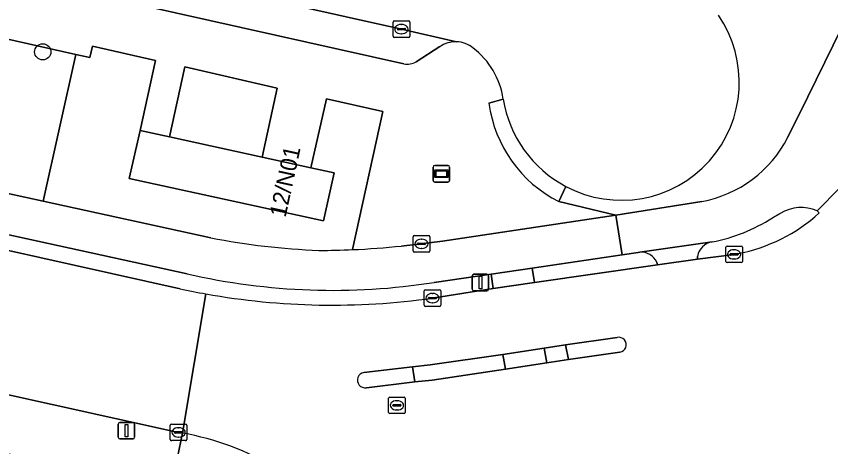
# Model space of a CAD drawing. Extents: x 162172 to 163187, y 382874 to 383685.
# Drawn here: x 163091.57 to 163140.66, y 383050.22 to 383076.16 of the extents above; entities that cross this region are included whole.
import ezdxf

# ---------------------------------------------------------------- set-up
doc = ezdxf.new("R2010")
doc.units = 0
for name, color, linetype in [('IMGEO_Boom', 7, 'Continuous'), ('IMGEO_Fietspad_gesloten', 7, 'Continuous'), ('IMGEO_Fietspad_open', 7, 'Continuous'), ('IMGEO_Groenvoorziening', 7, 'Continuous'), ('IMGEO_Kolk', 7, 'Continuous'), ('IMGEO_Lichtmast', 7, 'Continuous'), ('IMGEO_Pand', 7, 'Continuous'), ('IMGEO_Pand_nummerreeks', 7, 'Continuous'), ('IMGEO_Parkeervlak_open', 7, 'Continuous'), ('IMGEO_Reclamebord', 7, 'Continuous'), ('IMGEO_Rijbaan_lokaal_open', 7, 'Continuous'), ('IMGEO_Rioolput', 7, 'Continuous'), ('IMGEO_Verkeerseiland_open', 7, 'Continuous'), ('IMGEO_Voetpad_open', 7, 'Continuous')]:
    doc.layers.add(name, color=color, linetype=linetype)

msp = doc.modelspace()

# ---------------------------------------------------------------- linework, layer by layer
at = {"layer": 'IMGEO_Boom'}
msp.add_circle((163093.168, 383074.016), 0.489, dxfattribs=at)
at = {"layer": 'IMGEO_Fietspad_gesloten'}
for points in [[(163141.655, 383070.479), (163142.74, 383072.633), (163146.448, 383080.356), (163148.365, 383084.318), (163146.149, 383085.407), (163145.965, 383085.037), (163145.894, 383084.798), (163139.273, 383071.309), (163138.078, 383068.874)], [(163139.843, 383064.427), (163142.592, 383067.222)], [(163132.882, 383064.992), (163127.711, 383064.172), (163128.08, 383061.776), (163129.047, 383061.92), (163129.15, 383061.935), (163133.511, 383062.561)], [(163137.148, 383064.014), (163137.618, 383064.27)]]:
    msp.add_lwpolyline(points, dxfattribs=at)
for centre, radius, start, end in [((163131.517, 383072.237), 7.372, 280.6668, 332.861), ((163138.875, 383062.299), 2.338, 65.5429, 122.5295), ((163131.558, 383072.727), 10.352, 280.873, 302.681)]:
    msp.add_arc(centre, radius, start, end, dxfattribs=at)
at = {"layer": 'IMGEO_Fietspad_open'}
for points in [[(163103.293, 383062.808), (163093.192, 383065.008), (163090.977, 383065.49), (163082.089, 383067.416), (163081.762, 383067.487), (163081.303, 383067.542), (163068.825, 383068.129), (163068.711, 383065.723), (163080.79, 383065.134), (163081.09, 383065.184), (163101.866, 383060.645)], [(163116.758, 383060.123), (163120.185, 383060.622), (163122.671, 383060.982), (163128.08, 383061.776), (163127.711, 383064.172), (163117.252, 383062.615), (163114.786, 383062.314)], [(163133.511, 383062.561), (163129.15, 383061.935)], [(163130.176, 383061.332), (163130.212, 383061.172), (163132.626, 383061.518), (163132.623, 383061.691)]]:
    msp.add_lwpolyline(points, dxfattribs=at)
for centre, radius, start, end in [((163111.44, 383104.583), 42.562, 258.9647, 267.8134), ((163133.678, 383061.503), 1.072, 98.957, 169.8698), ((163109.817, 383108.459), 46.407, 269.9992, 272.4952), ((163109.816, 383109.488), 47.435, 272.4416, 276.014), ((163129.244, 383060.921), 1.019, 23.8194, 95.2934), ((163110.657, 383098.743), 39.099, 257.0073, 278.9777)]:
    msp.add_arc(centre, radius, start, end, dxfattribs=at)
at = {"layer": 'IMGEO_Groenvoorziening'}
for points in [[(163083.826, 383075.447), (163082.948, 383071.199), (163082.089, 383067.416), (163090.977, 383065.49), (163093.192, 383065.008), (163095.164, 383073.865), (163084.973, 383076.149)], [(163111.837, 383062.096), (163113.664, 383070.428), (163110.26, 383071.188), (163109.324, 383067.025), (163110.721, 383066.718), (163110.085, 383063.826), (163098.375, 383066.376), (163099.033, 383069.286), (163099.956, 383073.497), (163096.159, 383074.363), (163096.009, 383073.676), (163095.164, 383073.865), (163093.192, 383065.008), (163103.293, 383062.808)]]:
    msp.add_lwpolyline(points, dxfattribs=at)
msp.add_lwpolyline([(163106.386, 383067.671), (163107.298, 383071.823), (163101.738, 383073.108), (163100.799, 383068.898)], close=True, dxfattribs=at)
for centre, radius, start, end in [((163111.44, 383104.583), 42.562, 258.9647, 267.8134), ((163109.817, 383108.459), 46.407, 269.9992, 272.4952)]:
    msp.add_arc(centre, radius, start, end, dxfattribs=at)
at = {"layer": 'IMGEO_Kolk'}
for p, q in [((163114.282, 383074.961), (163114.282, 383075.813)), ((163114.357, 383075.887), (163115.209, 383075.887)), ((163114.77, 383075.667), (163114.795, 383075.667)), ((163115.283, 383075.813), (163115.283, 383074.961)), ((163114.541, 383075.381), (163114.541, 383075.393)), ((163114.979, 383075.344), (163114.581, 383075.344)), ((163114.584, 383075.43), (163114.982, 383075.43)), ((163115.025, 383075.393), (163115.025, 383075.381)), ((163115.209, 383074.887), (163114.357, 383074.887)), ((163114.793, 383075.107), (163114.768, 383075.107)), ((163115.57, 383062.946), (163116.422, 383062.946)), ((163115.495, 383062.02), (163115.495, 383062.872)), ((163115.754, 383062.44), (163115.754, 383062.452)), ((163116.192, 383062.403), (163115.794, 383062.403)), ((163115.797, 383062.489), (163116.195, 383062.489)), ((163115.983, 383062.726), (163116.008, 383062.726)), ((163116.238, 383062.452), (163116.238, 383062.44)), ((163116.496, 383062.872), (163116.496, 383062.02)), ((163116.422, 383061.946), (163115.57, 383061.946)), ((163116.006, 383062.166), (163115.981, 383062.166)), ((163134.333, 383061.387), (163134.333, 383062.239)), ((163134.408, 383062.313), (163135.26, 383062.313)), ((163134.821, 383062.093), (163134.846, 383062.093)), ((163135.334, 383062.239), (163135.334, 383061.387)), ((163134.592, 383061.807), (163134.592, 383061.819)), ((163135.03, 383061.77), (163134.632, 383061.77)), ((163134.635, 383061.856), (163135.033, 383061.856)), ((163134.844, 383061.533), (163134.819, 383061.533)), ((163135.076, 383061.819), (163135.076, 383061.807)), ((163135.26, 383061.313), (163134.408, 383061.313)), ((163116.156, 383058.753), (163116.156, 383059.605)), ((163116.231, 383059.679), (163117.083, 383059.679)), ((163116.644, 383059.459), (163116.669, 383059.459)), ((163117.157, 383059.605), (163117.157, 383058.753)), ((163116.415, 383059.173), (163116.415, 383059.185)), ((163116.853, 383059.136), (163116.455, 383059.136)), ((163116.458, 383059.222), (163116.856, 383059.222)), ((163116.899, 383059.185), (163116.899, 383059.173)), ((163117.083, 383058.679), (163116.231, 383058.679)), ((163116.667, 383058.899), (163116.642, 383058.899)), ((163100.853, 383050.659), (163100.853, 383051.511)), ((163100.928, 383051.585), (163101.78, 383051.585)), ((163101.155, 383051.128), (163101.553, 383051.128)), ((163101.341, 383051.365), (163101.366, 383051.365)), ((163101.854, 383051.511), (163101.854, 383050.659)), ((163101.112, 383051.079), (163101.112, 383051.091)), ((163101.55, 383051.042), (163101.152, 383051.042)), ((163101.364, 383050.805), (163101.339, 383050.805)), ((163101.596, 383051.091), (163101.596, 383051.079)), ((163101.78, 383050.585), (163100.928, 383050.585))]:
    msp.add_line(p, q, dxfattribs=at)
for points in [[(163114.282, 383074.961), (163114.282, 383075.813)], [(163114.357, 383075.887), (163115.209, 383075.887)], [(163115.283, 383075.813), (163115.283, 383074.961)], [(163115.209, 383074.887), (163114.357, 383074.887)], [(163115.57, 383062.946), (163116.422, 383062.946)], [(163115.495, 383062.02), (163115.495, 383062.872)], [(163116.496, 383062.872), (163116.496, 383062.02)], [(163116.422, 383061.946), (163115.57, 383061.946)], [(163134.333, 383061.387), (163134.333, 383062.239)], [(163134.408, 383062.313), (163135.26, 383062.313)], [(163135.334, 383062.239), (163135.334, 383061.387)], [(163135.26, 383061.313), (163134.408, 383061.313)], [(163116.156, 383058.753), (163116.156, 383059.605)], [(163116.231, 383059.679), (163117.083, 383059.679)], [(163117.157, 383059.605), (163117.157, 383058.753)], [(163117.083, 383058.679), (163116.231, 383058.679)], [(163100.853, 383050.659), (163100.853, 383051.511)], [(163100.928, 383051.585), (163101.78, 383051.585)], [(163101.854, 383051.511), (163101.854, 383050.659)], [(163101.78, 383050.585), (163100.928, 383050.585)]]:
    msp.add_lwpolyline(points, dxfattribs=at)
for centre, radius, start, end in [((163114.359, 383075.811), 0.0765, 91.552, 178.448), ((163114.359, 383075.811), 0.0765, 91.552, 178.448), ((163115.207, 383075.811), 0.0765, 1.552, 88.448), ((163115.207, 383075.811), 0.0765, 1.552, 88.448), ((163114.581, 383075.39), 0.0403, 85.8775, 175.7526), ((163114.578, 383075.38), 0.0366, 178.938, 274.7102), ((163114.982, 383075.387), 0.043, 264.8664, 352.4533), ((163114.986, 383075.392), 0.0386, 1.7309, 96.639), ((163114.359, 383074.963), 0.0765, 181.552, 268.448), ((163114.359, 383074.963), 0.0765, 181.552, 268.448), ((163115.207, 383074.963), 0.0765, 271.552, 358.448), ((163115.207, 383074.963), 0.0765, 271.552, 358.448), ((163115.572, 383062.87), 0.0765, 91.552, 178.448), ((163115.572, 383062.87), 0.0765, 91.552, 178.448), ((163116.42, 383062.87), 0.0765, 1.552, 88.448), ((163116.42, 383062.87), 0.0765, 1.552, 88.448), ((163115.794, 383062.449), 0.0403, 85.8775, 175.7526), ((163115.791, 383062.439), 0.0366, 178.938, 274.7102), ((163116.195, 383062.446), 0.043, 264.8664, 352.4533), ((163116.199, 383062.451), 0.0386, 1.7309, 96.639), ((163115.572, 383062.022), 0.0765, 181.552, 268.448), ((163115.572, 383062.022), 0.0765, 181.552, 268.448), ((163116.42, 383062.022), 0.0765, 271.552, 358.448), ((163116.42, 383062.022), 0.0765, 271.552, 358.448), ((163134.41, 383062.237), 0.0765, 91.552, 178.448), ((163134.41, 383062.237), 0.0765, 91.552, 178.448), ((163135.258, 383062.237), 0.0765, 1.552, 88.448), ((163135.258, 383062.237), 0.0765, 1.552, 88.448), ((163134.632, 383061.816), 0.0403, 85.8775, 175.7526), ((163134.629, 383061.806), 0.0366, 178.938, 274.7102), ((163135.033, 383061.813), 0.043, 264.8664, 352.4533), ((163135.037, 383061.818), 0.0386, 1.7309, 96.639), ((163134.41, 383061.389), 0.0765, 181.552, 268.448), ((163134.41, 383061.389), 0.0765, 181.552, 268.448), ((163135.258, 383061.389), 0.0765, 271.552, 358.448), ((163135.258, 383061.389), 0.0765, 271.552, 358.448), ((163116.233, 383059.603), 0.0765, 91.552, 178.448), ((163116.233, 383059.603), 0.0765, 91.552, 178.448), ((163117.081, 383059.603), 0.0765, 1.552, 88.448), ((163117.081, 383059.603), 0.0765, 1.552, 88.448), ((163116.455, 383059.182), 0.0403, 85.8775, 175.7526), ((163116.452, 383059.172), 0.0366, 178.938, 274.7102), ((163116.856, 383059.179), 0.043, 264.8664, 352.4533), ((163116.86, 383059.184), 0.0386, 1.7309, 96.639), ((163116.233, 383058.755), 0.0765, 181.552, 268.448), ((163116.233, 383058.755), 0.0765, 181.552, 268.448), ((163117.081, 383058.755), 0.0765, 271.552, 358.448), ((163117.081, 383058.755), 0.0765, 271.552, 358.448), ((163100.93, 383051.509), 0.0765, 91.552, 178.448), ((163100.93, 383051.509), 0.0765, 91.552, 178.448), ((163101.152, 383051.088), 0.0403, 85.8775, 175.7526), ((163101.557, 383051.09), 0.0386, 1.7309, 96.639), ((163101.778, 383051.509), 0.0765, 1.552, 88.448), ((163101.778, 383051.509), 0.0765, 1.552, 88.448), ((163100.93, 383050.661), 0.0765, 181.552, 268.448), ((163100.93, 383050.661), 0.0765, 181.552, 268.448), ((163101.149, 383051.078), 0.0366, 178.938, 274.7102), ((163101.553, 383051.085), 0.043, 264.8664, 352.4533), ((163101.778, 383050.661), 0.0765, 271.552, 358.448), ((163101.778, 383050.661), 0.0765, 271.552, 358.448)]:
    msp.add_arc(centre, radius, start, end, dxfattribs=at)
for centre, major_axis, ratio, start_param, end_param in [((163114.769, 383075.387), (-0.387, 0.002), 0.722429, 4.712389, 7.853982), ((163114.794, 383075.387), (-0.39, 0.002), 0.717154, 1.570796, 4.712389), ((163115.982, 383062.446), (-0.387, 0.002), 0.722429, 4.712389, 7.853982), ((163116.007, 383062.446), (-0.39, 0.002), 0.717154, 1.570796, 4.712389), ((163134.82, 383061.813), (-0.387, 0.002), 0.722429, 4.712389, 7.853982), ((163134.845, 383061.813), (-0.39, 0.002), 0.717154, 1.570796, 4.712389), ((163116.643, 383059.179), (-0.387, 0.002), 0.722429, 4.712389, 7.853982), ((163116.668, 383059.179), (-0.39, 0.002), 0.717154, 1.570796, 4.712389), ((163101.34, 383051.085), (-0.387, 0.002), 0.722429, 4.712389, 7.853982), ((163101.365, 383051.085), (-0.39, 0.002), 0.717154, 1.570796, 4.712389)]:
    msp.add_ellipse(centre, major_axis=major_axis, ratio=ratio, start_param=start_param, end_param=end_param, dxfattribs=at)
at = {"layer": 'IMGEO_Lichtmast'}
for p, q in [((163119.051, 383059.713), (163119.051, 383060.513)), ((163119.051, 383060.513), (163119.051, 383059.713)), ((163119.151, 383060.613), (163119.941, 383060.613)), ((163119.941, 383060.613), (163119.151, 383060.613)), ((163120.041, 383060.513), (163120.041, 383059.713)), ((163120.041, 383059.713), (163120.041, 383060.513)), ((163119.941, 383059.613), (163119.151, 383059.613)), ((163119.151, 383059.613), (163119.941, 383059.613)), ((163097.817, 383051.686), (163098.607, 383051.686)), ((163098.607, 383051.686), (163097.817, 383051.686)), ((163097.717, 383050.786), (163097.717, 383051.586)), ((163097.717, 383051.586), (163097.717, 383050.786)), ((163098.707, 383051.586), (163098.707, 383050.786)), ((163098.707, 383050.786), (163098.707, 383051.586)), ((163098.607, 383050.686), (163097.817, 383050.686)), ((163097.817, 383050.686), (163098.607, 383050.686))]:
    msp.add_line(p, q, dxfattribs=at)
for points in [[(163119.471, 383060.488), (163119.621, 383060.488), (163119.621, 383059.738), (163119.471, 383059.738), (163119.471, 383060.488)], [(163098.137, 383051.561), (163098.287, 383051.561), (163098.287, 383050.811), (163098.137, 383050.811), (163098.137, 383051.561)]]:
    msp.add_lwpolyline(points, dxfattribs=at)
for centre, start, end in [((163119.151, 383060.513), 90, 180), ((163119.151, 383060.513), 90, 180), ((163119.941, 383060.513), 0, 90), ((163119.941, 383060.513), 360, 90), ((163119.151, 383059.713), 180, 270), ((163119.151, 383059.713), 180, 270), ((163119.941, 383059.713), 270, 0), ((163119.941, 383059.713), 270, 0), ((163097.817, 383051.586), 90, 180), ((163097.817, 383051.586), 90, 180), ((163098.607, 383051.586), 0, 90), ((163098.607, 383051.586), 360, 90), ((163097.817, 383050.786), 180, 270), ((163097.817, 383050.786), 180, 270), ((163098.607, 383050.786), 270, 0), ((163098.607, 383050.786), 270, 0)]:
    msp.add_arc(centre, 0.1, start, end, dxfattribs=at)
at = {"layer": 'IMGEO_Pand'}
msp.add_lwpolyline([(163106.386, 383067.671), (163100.799, 383068.898), (163099.033, 383069.286), (163098.375, 383066.376), (163110.085, 383063.826), (163110.721, 383066.718), (163109.324, 383067.025)], close=True, dxfattribs=at)
at = {"layer": 'IMGEO_Parkeervlak_open'}
for points in [[(163118.106, 383074.625), (163114.783, 383075.388), (163095.322, 383079.742)], [(163093.433, 383078.115), (163114.935, 383073.286)], [(163115.671, 383073.409), (163117.096, 383074.329)]]:
    msp.add_lwpolyline(points, dxfattribs=at)
for centre, radius, start, end in [((163118.056, 383072.924), 1.701, 88.3172, 124.3513), ((163115.092, 383074.61), 1.333, 263.2379, 295.7372)]:
    msp.add_arc(centre, radius, start, end, dxfattribs=at)
at = {"layer": 'IMGEO_Reclamebord'}
for p, q in [((163116.693, 383066.267), (163116.693, 383067.067)), ((163116.693, 383067.067), (163116.693, 383066.267)), ((163116.793, 383067.167), (163117.583, 383067.167)), ((163117.583, 383067.167), (163116.793, 383067.167)), ((163117.683, 383067.067), (163117.683, 383066.267)), ((163117.683, 383066.267), (163117.683, 383067.067)), ((163117.583, 383066.167), (163116.793, 383066.167)), ((163116.793, 383066.167), (163117.583, 383066.167))]:
    msp.add_line(p, q, dxfattribs=at)
for points in [[(163116.794, 383066.899), (163117.582, 383066.899), (163117.582, 383066.435), (163116.794, 383066.435), (163116.794, 383066.899)], [(163116.859, 383066.834), (163116.859, 383066.5), (163117.517, 383066.5), (163117.517, 383066.834), (163116.859, 383066.834)]]:
    msp.add_lwpolyline(points, dxfattribs=at)
for centre, start, end in [((163116.793, 383067.067), 90, 180), ((163116.793, 383067.067), 90, 180), ((163117.583, 383067.067), 0, 90), ((163117.583, 383067.067), 360, 90), ((163116.793, 383066.267), 180, 270), ((163116.793, 383066.267), 180, 270), ((163117.583, 383066.267), 270, 0), ((163117.583, 383066.267), 270, 0)]:
    msp.add_arc(centre, 0.1, start, end, dxfattribs=at)
at = {"layer": 'IMGEO_Rijbaan_lokaal_open'}
for points in [[(162923.801, 383089.955), (162943.612, 383085.806), (162967.521, 383080.514), (162978.531, 383078.074), (162981.3, 383077.468), (162988.164, 383075.862), (163003.235, 383072.524), (163027.464, 383067.193), (163035.8, 383065.359), (163048.436, 383062.578), (163059.491, 383060.146), (163068.103, 383058.359), (163078.69, 383056.046), (163084.272, 383054.851), (163086.106, 383054.458), (163101.354, 383051.086), (163101.592, 383051.043), (163103.004, 383059.429)], [(163131.436, 383076.871), (163117.964, 383079.829), (163095.935, 383084.747), (163092.25, 383085.659), (163091.169, 383080.659), (163095.322, 383079.742), (163114.783, 383075.388), (163118.106, 383074.625)], [(163120.918, 383071.173), (163120.061, 383070.914)], [(163142.592, 383067.222), (163139.843, 383064.427), (163139.969, 383064.315)], [(163124.262, 383064.991), (163124.696, 383065.906)], [(163101.445, 383059.739), (163090.916, 383062.089), (163080.888, 383064.291)], [(163135.061, 383061.86), (163134.834, 383061.812), (163132.626, 383061.518), (163130.212, 383061.172), (163122.812, 383060.11), (163120.318, 383059.75), (163116.657, 383059.178)], [(163103.004, 383059.429), (163101.592, 383051.043)], [(163112.519, 383054.695), (163115.459, 383055.027), (163116.509, 383055.146), (163120.899, 383055.786), (163123.382, 383056.152), (163124.675, 383056.355), (163127.792, 383056.809)], [(163127.942, 383055.92), (163124.846, 383055.466), (163123.541, 383055.268), (163121.052, 383054.887), (163116.637, 383054.234), (163115.602, 383054.138)], [(163115.602, 383054.138), (163112.674, 383053.778)]]:
    msp.add_lwpolyline(points, dxfattribs=at)
for centre, radius, start, end in [((163128.036, 383072.181), 7.109, 241.9753, 34.5978), ((163118.052, 383072.989), 1.637, 50.1734, 88.1225), ((163116.254, 383070.489), 4.714, 8.3447, 52.8452), ((163127.84, 383071.98), 7.852, 187.8049, 242.8889), ((163128.088, 383072.328), 7.263, 189.1482, 242.1553), ((163128.088, 383072.328), 7.263, 189.1482, 242.1553), ((163133.191, 383071.732), 10.048, 280.7262, 312.4226), ((163110.829, 383102.854), 44.124, 257.7216, 259.7857), ((163110.611, 383101.749), 42.998, 259.8101, 278.0835), ((163127.878, 383056.366), 0.451, 278.123, 101.0315), ((163112.595, 383054.236), 0.465, 99.3515, 279.8365), ((163098.681, 383034.784), 16.518, 58.9041, 79.8498)]:
    msp.add_arc(centre, radius, start, end, dxfattribs=at)
at = {"layer": 'IMGEO_Rioolput'}
for p, q in [((163114.013, 383052.287), (163114.013, 383053.139)), ((163114.088, 383053.213), (163114.94, 383053.213)), ((163115.014, 383053.139), (163115.014, 383052.287)), ((163114.272, 383052.707), (163114.272, 383052.719)), ((163114.71, 383052.67), (163114.312, 383052.67)), ((163114.315, 383052.756), (163114.713, 383052.756)), ((163114.501, 383052.993), (163114.526, 383052.993)), ((163114.756, 383052.719), (163114.756, 383052.707)), ((163114.94, 383052.213), (163114.088, 383052.213)), ((163114.524, 383052.433), (163114.499, 383052.433))]:
    msp.add_line(p, q, dxfattribs=at)
for points in [[(163114.013, 383052.287), (163114.013, 383053.139)], [(163114.088, 383053.213), (163114.94, 383053.213)], [(163115.014, 383053.139), (163115.014, 383052.287)], [(163114.94, 383052.213), (163114.088, 383052.213)]]:
    msp.add_lwpolyline(points, dxfattribs=at)
for centre, radius, start, end in [((163114.09, 383053.137), 0.0765, 91.552, 178.448), ((163114.09, 383053.137), 0.0765, 91.552, 178.448), ((163114.938, 383053.137), 0.0765, 1.552, 88.448), ((163114.938, 383053.137), 0.0765, 1.552, 88.448), ((163114.312, 383052.716), 0.0403, 85.8775, 175.7526), ((163114.309, 383052.706), 0.0366, 178.938, 274.7102), ((163114.713, 383052.713), 0.043, 264.8664, 352.4533), ((163114.717, 383052.718), 0.0386, 1.7309, 96.639), ((163114.09, 383052.289), 0.0765, 181.552, 268.448), ((163114.09, 383052.289), 0.0765, 181.552, 268.448), ((163114.938, 383052.289), 0.0765, 271.552, 358.448), ((163114.938, 383052.289), 0.0765, 271.552, 358.448)]:
    msp.add_arc(centre, radius, start, end, dxfattribs=at)
for centre, major_axis, ratio, start_param, end_param in [((163114.5, 383052.713), (-0.387, 0.002), 0.722429, 4.712389, 7.853982), ((163114.525, 383052.713), (-0.39, 0.002), 0.717154, 1.570796, 4.712389)]:
    msp.add_ellipse(centre, major_axis=major_axis, ratio=ratio, start_param=start_param, end_param=end_param, dxfattribs=at)
at = {"layer": 'IMGEO_Verkeerseiland_open'}
for points in [[(163101.866, 383060.645), (163081.09, 383065.184)], [(163139.969, 383064.315), (163139.843, 383064.427)], [(163080.888, 383064.291), (163090.916, 383062.089), (163101.445, 383059.739)], [(163137.618, 383064.27), (163137.148, 383064.014)], [(163129.15, 383061.935), (163129.047, 383061.92), (163128.08, 383061.776), (163122.671, 383060.982), (163122.812, 383060.11), (163130.212, 383061.172), (163130.176, 383061.332)], [(163132.623, 383061.691), (163132.626, 383061.518), (163134.834, 383061.812), (163135.061, 383061.86)], [(163116.657, 383059.178), (163120.318, 383059.75), (163120.185, 383060.622), (163116.758, 383060.123)], [(163127.792, 383056.809), (163124.675, 383056.355), (163124.846, 383055.466), (163127.942, 383055.92)], [(163112.674, 383053.778), (163115.602, 383054.138), (163115.459, 383055.027), (163112.519, 383054.695)]]:
    msp.add_lwpolyline(points, dxfattribs=at)
for points in [[(163123.382, 383056.152), (163123.541, 383055.268), (163124.846, 383055.466), (163124.675, 383056.355)], [(163115.459, 383055.027), (163115.602, 383054.138), (163116.637, 383054.234), (163121.052, 383054.887), (163120.899, 383055.786), (163116.509, 383055.146)]]:
    msp.add_lwpolyline(points, close=True, dxfattribs=at)
for centre, radius, start, end in [((163138.875, 383062.299), 2.338, 65.5429, 122.5295), ((163131.558, 383072.727), 10.352, 280.873, 302.681), ((163133.191, 383071.732), 10.048, 280.7262, 312.4226), ((163133.678, 383061.503), 1.072, 98.957, 169.8698), ((163129.244, 383060.921), 1.019, 23.8194, 95.2934), ((163110.657, 383098.743), 39.099, 257.0073, 278.9777), ((163110.829, 383102.854), 44.124, 257.7216, 259.7857), ((163110.611, 383101.749), 42.998, 259.8101, 278.0835), ((163127.878, 383056.366), 0.451, 278.123, 101.0315), ((163112.595, 383054.236), 0.465, 99.3515, 279.8365)]:
    msp.add_arc(centre, radius, start, end, dxfattribs=at)
at = {"layer": 'IMGEO_Voetpad_open'}
for points in [[(163138.078, 383068.874), (163139.273, 383071.309), (163145.894, 383084.798), (163145.965, 383085.037), (163146.149, 383085.407), (163149.186, 383091.519), (163151.057, 383095.321), (163151.108, 383095.433), (163151.151, 383095.548), (163151.242, 383096.399), (163149.619, 383097.129), (163150.212, 383098.424), (163150.509, 383098.304)], [(163114.935, 383073.286), (163093.433, 383078.115)], [(163084.973, 383076.149), (163095.164, 383073.865), (163096.009, 383073.676), (163096.159, 383074.363), (163099.956, 383073.497), (163099.033, 383069.286), (163100.799, 383068.898), (163101.738, 383073.108), (163107.298, 383071.823), (163106.386, 383067.671), (163109.324, 383067.025), (163110.26, 383071.188), (163113.664, 383070.428), (163111.837, 383062.096)], [(163117.096, 383074.329), (163115.671, 383073.409)], [(163120.061, 383070.914), (163120.918, 383071.173)], [(163124.696, 383065.906), (163124.262, 383064.991), (163127.711, 383064.172), (163132.882, 383064.992)], [(163114.786, 383062.314), (163117.252, 383062.615), (163127.711, 383064.172), (163124.262, 383064.991)], [(163101.197, 383049.116), (163101.592, 383051.043), (163101.354, 383051.086), (163086.106, 383054.458), (163084.272, 383054.851), (163083.554, 383051.437), (163088.206, 383050.416), (163090.563, 383049.905), (163100.899, 383047.662), (163102.739, 383047.263)], [(163101.592, 383051.043), (163101.197, 383049.116)]]:
    msp.add_lwpolyline(points, dxfattribs=at)
for points in [[(163122.671, 383060.982), (163120.185, 383060.622), (163120.318, 383059.75), (163122.812, 383060.11)], [(163123.382, 383056.152), (163120.899, 383055.786), (163121.052, 383054.887), (163123.541, 383055.268)]]:
    msp.add_lwpolyline(points, close=True, dxfattribs=at)
for centre, radius, start, end in [((163128.036, 383072.181), 7.109, 241.9753, 34.5978), ((163118.056, 383072.924), 1.701, 88.3172, 124.3513), ((163118.052, 383072.989), 1.637, 50.1734, 88.1225), ((163116.254, 383070.489), 4.714, 8.3447, 52.8452), ((163115.092, 383074.61), 1.333, 263.2379, 295.7372), ((163127.84, 383071.98), 7.852, 187.8049, 242.8889), ((163131.517, 383072.237), 7.372, 280.6668, 332.861), ((163109.816, 383109.488), 47.435, 272.4416, 276.014), ((163098.681, 383034.784), 16.518, 58.9041, 79.8498)]:
    msp.add_arc(centre, radius, start, end, dxfattribs=at)

# ---------------------------------------------------------------- texts
at = {"layer": 'IMGEO_Pand_nummerreeks'}
msp.add_text('12/N01', height=1, rotation=77.7352, dxfattribs=at).set_placement((163107.797, 383063.997))

doc.saveas('drawing.dxf')
